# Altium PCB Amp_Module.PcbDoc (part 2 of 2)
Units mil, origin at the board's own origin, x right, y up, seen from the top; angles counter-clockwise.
Board outline 3270 x 1420 mil, 4 copper layers (Top Layer, InternalPlane1, InternalPlane2, Bottom Layer), stack 58.358 mil thick; 81 components, 51 nets, 288 pads, 46 vias.
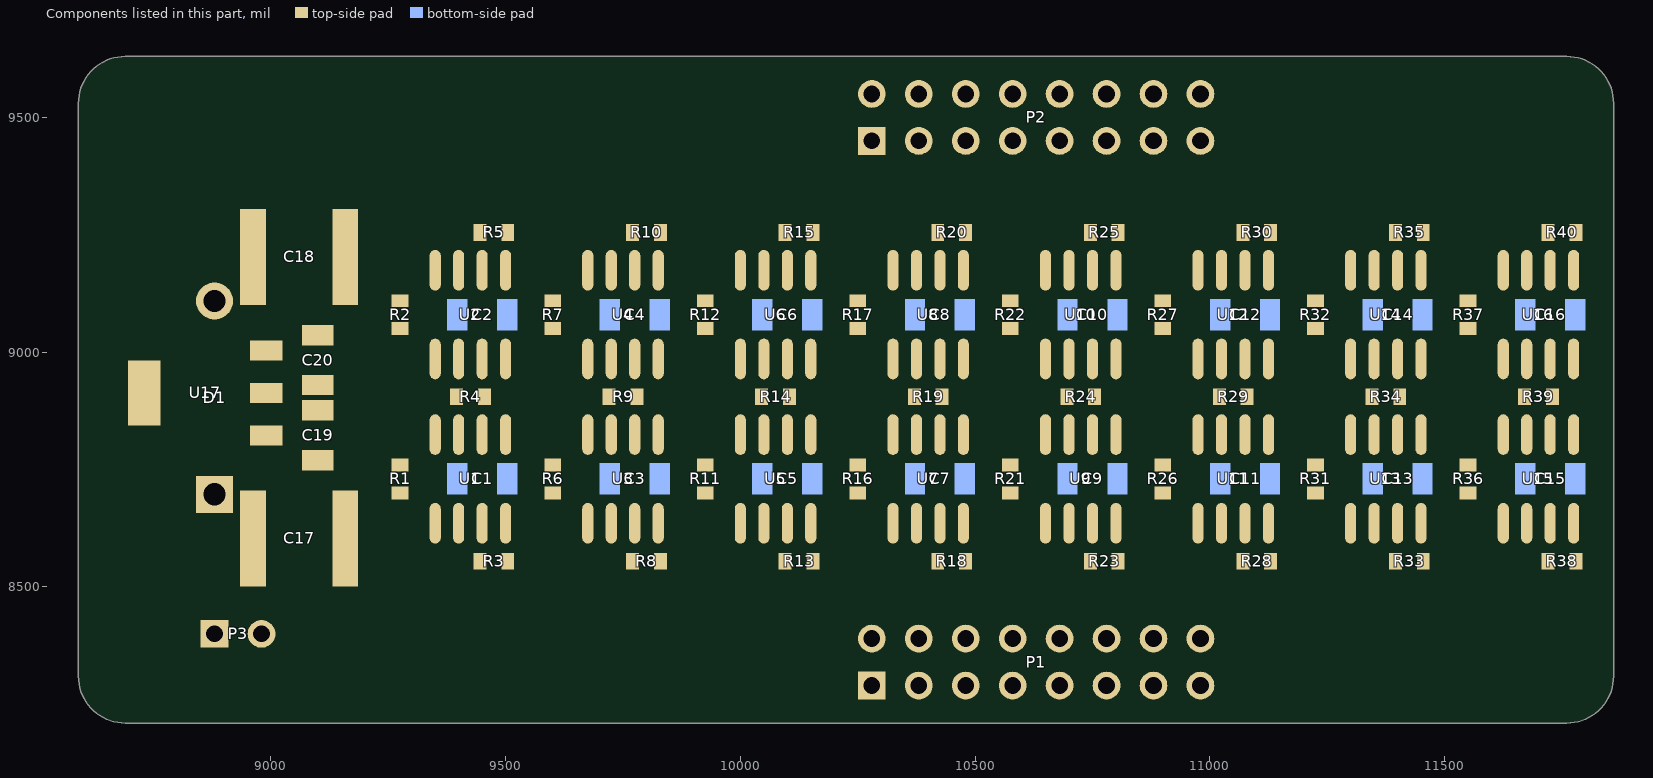
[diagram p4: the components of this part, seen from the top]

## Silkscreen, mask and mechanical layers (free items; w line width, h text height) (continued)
Mechanical 7:
  drawing of 1016 lines, arcs and shapes, not listed
  text "1" at 2126,16181 h118
  text "2" at 4960,16181 h118
  text "3" at 7795,16181 h118
  text "4" at 10511,16181 h118
  text "5" at 13346,16181 h118
  text "6" at 16102,16181 h118
  text "7" at 18937,16181 h118
  text "8" at 21850,16181 h118
  text "NANOBOARD" at 1660,15683 h120
  text "DT01.02" at 4818.75,15679.48 h140
  text "A" at 826,14921 h118
  text "A" at 23031,14921 h118
  text "IDENTIFICATION DATA" at 13932.98,12681.05 h40
  text "B" at 846,12166 h118
  text "B" at 23051,12166 h118
  text "C" at 846,9606 h118
  text "C" at 23051,9606 h118
  text "D" at 846,6890 h118
  text "D" at 23051,6890 h118
  text "mm" at 591,6496 h79 r90
  text "E" at 846,4232 h118
  text "E" at 23051,4232 h118
  text "0" at 591,2441 h79 r90
  text "DO NOT" at 217,1890 h79
  text "SCALE" at 236,1752 h79
  text "DIMENSIONS" at 98,1555 h79
  text "F" at 846,1516 h118
  text "F" at 23051,1516 h118
  text "SCALE:" at 21376.7,1457.08 h70
  text "ALTIUM LIMITED" at 15308.95,1440.88 h70
  text "DESIGNER" at 14414.66,1438.71 h70
  text "DATE" at 16887.86,1434.08 h70
  text "LEVEL 3 / 12A RODBOROUGH ROAD" at 18204.55,1429.54 h62.99
  text "IN" at 354,1417 h79
  text "FRENCHS FOREST - SYDNEY 2086" at 18202.77,1335.16 h62.99
  text ".Print_Scale" at 21772.96,1282.87 h100
  text "MILLIMETRES" at 79,1260 h79
  text "NSW AUSTRALIA" at 18203.95,1247.12 h62.99
  text "DRAWN" at 14412.86,1241.08 h70
  text "08.SEPT.07" at 16785.96,1236.87 h70
  text "Steven. R. Howell" at 15307.66,1235.71 h70
  text "DATE:" at 21373.7,1063.37 h70
  text "01.APR.08" at 13793.91,1052.03 h70
  text "UPDATED WITH HOT PLUG CAPABILITY" at 7977.85,1050.85 h70
  text "S.HOWELL" at 13214.84,1048.84 h70
  text "2" at 7486.86,1046.83 h70
  text "CHECKED" at 14412.86,1047.08 h70
  text "Steven. R. Howell" at 15301.96,1042.87 h70
  text "INDEX" at 17555.96,1042.87 h70
  text "08.SEPT.07" at 16785.96,1036.87 h70
  text ".Print_Date" at 21742.96,907.87 h100
  text "08.SEPT.07" at 13793.91,854.03 h70
  text "DESIGN CREATED" at 7977.85,852.85 h70
  text "S.HOWELL" at 13214.84,850.84 h70
  text "1" at 7486.86,848.83 h70
  text "ALTIUM DEVELOPMENT PRODUCTS" at 15655.96,848.87 h70
  text "CUSTOMER" at 14410.96,839.87 h70
  text "Title:" at 17558.86,835.78 h80
  text "SHEET" at 21377.17,669.67 h70
  text "DT01.01 - DEVELOPMENT TOOL 01.02" at 17572.97,662.85 h90
  text "REVISION" at 7337.84,651.84 h70
  text "DESCRIPTION OF TASK OR MODIFICATION" at 10159.84,651.84 h70
  text "DATE" at 13896.73,632.67 h70
  text "APPD" at 13306.18,630.42 h70
  text "A2" at 22728.86,544.08 h78.74
  text ".Pcb_File_Name" at 9629.96,463.9 h70
  text ".Printout_Name" at 8024.96,448.87 h70
  text "TEMPLATE: -" at 7337.84,446.84 h70
  text "1" at 2126,236 h118
  text "2" at 4960,236 h118
  text "3" at 7795,236 h118
  text "4" at 10511,236 h118
  text "5" at 13346,236 h118
  text "6" at 16102,236 h118
  text "7" at 18937,236 h118
  text "8" at 21850,236 h118
Mechanical 15:
  rectangle: 13672.98,12536.05 13862.98,12631.05
  lines w5: 13672.98,12536.05 13672.98,12631.05 14592.98,12631.05 14592.98,12536.05 13672.98,12536.05
  text "DIMENSIONS" at 13932.98,12563.05 h40
Drill Drawing:
  rectangle: 13672.98,13244.05 13862.98,13339.05
  lines w5: 13672.98,13244.05 13672.98,13339.05 14592.98,13339.05 14592.98,13244.05 13672.98,13244.05
  text "DRILL DRAWING" at 13932.98,13271.05 h40
  text ".Legend" at 1120.03,501.08 h68.9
